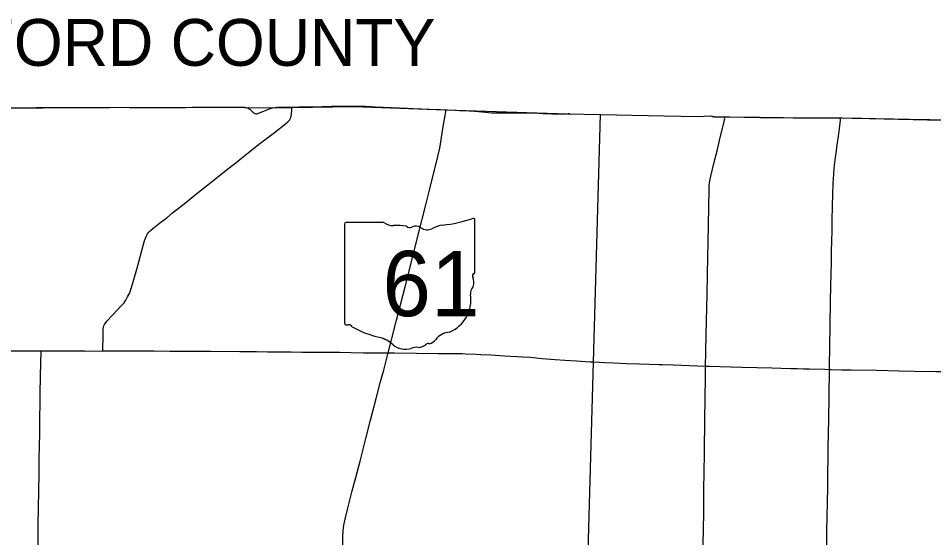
# Model space of a CAD drawing. Extents: x 1815539 to 1947826, y 273303 to 993194.
# Drawn here: x 1872474 to 1891996, y 979080 to 990160 of the extents above; entities that cross this region are included whole.
import ezdxf

# ---------------------------------------------------------------- set-up
doc = ezdxf.new("R2010")
doc.units = 0
for name, color, linetype in [('GM_X_Adjacent_County_Text', 7, 'Continuous'), ('GM_X_County', 7, 'Continuous'), ('GM_X_County_Road', 7, 'Continuous'), ('GM_X_State_Route', 7, 'Continuous'), ('GM_X_Township', 7, 'Continuous'), ('GM_X_Township_Road', 7, 'Continuous'), ('SC_Shading3', 7, 'Continuous')]:
    doc.layers.add(name, color=color, linetype=linetype)

msp = doc.modelspace()

# ---------------------------------------------------------------- linework, layer by layer
at = {"layer": 'GM_X_County'}
msp.add_lwpolyline([(1871661, 988243), (1875677, 988261), (1877300, 988258), (1877944, 988247), (1878309, 988257), (1879625, 988278), (1881591, 988207), (1884186, 988121), (1884889, 988110), (1886245, 988079), (1886959, 988065), (1887247, 988078), (1887277, 988068), (1887305, 988061), (1887332, 988057), (1887406, 988055), (1887534, 988056), (1887954, 988052), (1888291, 988047), (1888567, 988043), (1888789, 988041), (1889241, 988035), (1890006, 988038), (1892176, 987990)], dxfattribs=at)
at = {"layer": 'GM_X_County_Road'}
for points in [[(1871661, 988242), (1871757, 988241), (1871923, 988244), (1872250, 988251), (1872857, 988256), (1873350, 988258), (1873629, 988258), (1873925, 988259), (1874253, 988259), (1874417, 988258), (1874663, 988261), (1874844, 988260), (1875139, 988257), (1875402, 988259), (1875632, 988258), (1875672, 988258)], [(1875672, 988258), (1875796, 988259), (1876042, 988260), (1876174, 988261), (1876404, 988261), (1876617, 988261), (1876880, 988261), (1877143, 988262), (1877257, 988263)], [(1887133, 982742), (1887138, 983036), (1887145, 983413), (1887162, 984266), (1887174, 984709), (1887183, 985054), (1887195, 985743), (1887201, 986153), (1887205, 986497), (1887210, 986595), (1887222, 986692), (1887240, 986789), (1887318, 987091), (1887384, 987361), (1887446, 987616), (1887528, 987951), (1887538, 988001), (1887539, 988021), (1887538, 988035), (1887537, 988057)], [(1887251, 988079), (1887281, 988069), (1887308, 988062), (1887336, 988058), (1887410, 988056), (1887537, 988057)], [(1889775, 982670), (1889775, 982731), (1889783, 983158), (1889789, 983601), (1889799, 984143), (1889810, 984733), (1889814, 984914), (1889818, 985176), (1889823, 985422), (1889829, 985618), (1889831, 985749), (1889832, 985864), (1889838, 986143), (1889847, 986405), (1889854, 986635), (1889864, 986832), (1889874, 986963), (1889889, 987077), (1889905, 987190), (1889919, 987287), (1889937, 987450), (1889971, 987693), (1890004, 987921), (1890008, 987985), (1890006, 987998), (1890002, 988008), (1889995, 988022), (1889986, 988034)], [(1871633, 983066), (1871767, 983066), (1872276, 983066), (1872489, 983068), (1872915, 983067), (1872959, 983067)], [(1872883, 977728), (1872885, 977952), (1872887, 978231), (1872890, 978559), (1872895, 979018), (1872900, 979346), (1872916, 980444), (1872921, 980789), (1872925, 981002), (1872930, 981330), (1872932, 981494), (1872936, 981707), (1872938, 981870), (1872943, 982198), (1872947, 982477), (1872954, 982854), (1872958, 983018), (1872958, 983035), (1872959, 983067)], [(1872959, 983067), (1873193, 983066), (1873489, 983064), (1873899, 983064), (1874243, 983062), (1874277, 983063)], [(1874277, 983063), (1874390, 983063), (1874964, 983063), (1875374, 983063), (1875702, 983061), (1876063, 983060), (1876572, 983057), (1877195, 983051), (1877555, 983049), (1877785, 983048), (1877916, 983047), (1878293, 983044), (1878523, 983041), (1878998, 983036), (1879326, 983034), (1879572, 983030), (1879834, 983026), (1880113, 983025), (1880309, 983024), (1880352, 983024), (1880363, 983024)], [(1887061, 977710), (1887063, 977813), (1887072, 978453), (1887082, 978978), (1887085, 979224), (1887088, 979339), (1887092, 979534), (1887093, 979696), (1887094, 979792), (1887097, 980100), (1887106, 980871), (1887117, 981642), (1887121, 982003), (1887131, 982544), (1887133, 982724), (1887133, 982742)], [(1889705, 978226), (1889707, 978335), (1889710, 978646), (1889714, 978942), (1889719, 979221), (1889736, 980140), (1889740, 980484), (1889743, 980763), (1889745, 980993), (1889754, 981320), (1889760, 981599), (1889766, 982092), (1889775, 982670)], [(1889775, 982670), (1889810, 982669), (1890039, 982664), (1890236, 982660), (1890777, 982650), (1891253, 982641), (1891581, 982635), (1892040, 982626), (1892187, 982623), (1892597, 982617), (1893007, 982610), (1893384, 982604), (1893613, 982600), (1893744, 982597), (1894021, 982589), (1894087, 982587), (1894268, 982583), (1894530, 982582), (1894793, 982578), (1894891, 982575), (1894907, 982574), (1894932, 982573)]]:
    msp.add_lwpolyline(points, dxfattribs=at)
at = {"layer": 'GM_X_State_Route'}
for points in [[(1881240, 986494), (1881241, 986497), (1881334, 986863), (1881422, 987213), (1881461, 987389), (1881493, 987567), (1881531, 987810), (1881599, 988208)], [(1880540, 983720), (1880575, 983857), (1880721, 984429), (1880849, 984938), (1881003, 985542), (1881164, 986179), (1881226, 986434), (1881240, 986494)], [(1880266, 982653), (1880282, 982713), (1880363, 983024), (1880434, 983300), (1880540, 983720)], [(1879887, 981197), (1879988, 981586), (1880058, 981856), (1880107, 982046), (1880194, 982380), (1880234, 982531), (1880266, 982653)], [(1879384, 977403), (1879392, 977559), (1879402, 977887), (1879403, 978084), (1879397, 978543), (1879395, 978855), (1879397, 979101), (1879405, 979231), (1879419, 979345), (1879443, 979474), (1879492, 979681), (1879595, 980078), (1879670, 980363), (1879762, 980712), (1879887, 981197)]]:
    msp.add_lwpolyline(points, dxfattribs=at)
at = {"layer": 'GM_X_Township'}
msp.add_lwpolyline([(1884254, 961672), (1884396, 966955), (1884454, 969588), (1884489, 972257), (1884586, 977269), (1884741, 982824), (1884889, 988110)], dxfattribs=at)
at = {"layer": 'GM_X_Township_Road'}
for points in [[(1876419, 986529), (1876483, 986580), (1876585, 986662), (1876827, 986858), (1876942, 986950), (1877110, 987080), (1877162, 987121), (1877302, 987234), (1877599, 987467), (1877936, 987727), (1878170, 987907), (1878220, 987949), (1878254, 987985), (1878272, 988012), (1878286, 988042), (1878296, 988073), (1878301, 988105), (1878306, 988220), (1878305, 988238), (1878304, 988253), (1878301, 988267)], [(1877257, 988263), (1877303, 988261), (1877325, 988258), (1877350, 988253), (1877377, 988243), (1877390, 988236), (1877413, 988218), (1877468, 988164), (1877493, 988143), (1877506, 988134), (1877520, 988127), (1877536, 988123), (1877552, 988123), (1877568, 988126), (1877583, 988130), (1877599, 988135), (1877691, 988171), (1877723, 988184), (1877829, 988225), (1877852, 988234), (1877901, 988248), (1877946, 988257)], [(1877946, 988257), (1877965, 988260), (1877973, 988260), (1877996, 988262), (1878029, 988264)], [(1878029, 988264), (1878045, 988265), (1878127, 988265), (1878301, 988267)], [(1878301, 988267), (1878457, 988268), (1878956, 988279), (1879160, 988283), (1879620, 988289)], [(1879620, 988289), (1879732, 988288), (1879880, 988284), (1879995, 988279), (1880093, 988274), (1880765, 988244), (1880896, 988237), (1881073, 988227), (1881237, 988220), (1881481, 988211), (1881559, 988209), (1881599, 988208)], [(1881599, 988208), (1881624, 988207), (1881788, 988198), (1881810, 988197)], [(1881810, 988197), (1881886, 988194), (1881979, 988190)], [(1881979, 988190), (1882082, 988186), (1882145, 988183), (1882209, 988181), (1882291, 988175), (1882356, 988168), (1882437, 988157), (1882503, 988151), (1882572, 988146), (1882642, 988145)], [(1882642, 988145), (1882730, 988143), (1882928, 988145), (1883051, 988143), (1883208, 988144), (1883339, 988142), (1883421, 988141), (1883568, 988136), (1883667, 988132), (1883847, 988125), (1883856, 988125)], [(1883856, 988125), (1883978, 988121), (1884093, 988120), (1884159, 988122), (1884208, 988126), (1884236, 988129)], [(1887537, 988057), (1887640, 988058), (1887958, 988053)], [(1887958, 988053), (1888295, 988048)], [(1888295, 988048), (1888461, 988045), (1888570, 988043)], [(1888570, 988043), (1888592, 988043), (1888773, 988042), (1888793, 988042)], [(1888793, 988042), (1889002, 988040), (1889239, 988037)], [(1889239, 988037), (1889574, 988034), (1889784, 988034), (1889833, 988034), (1889931, 988034), (1889986, 988034)], [(1889986, 988034), (1890029, 988033), (1890044, 988033)], [(1890044, 988033), (1890260, 988031), (1890461, 988028), (1890755, 988021), (1891138, 988014), (1891484, 988007), (1891917, 987998), (1892166, 987992)], [(1874277, 983063), (1874277, 983094), (1874280, 983373), (1874283, 983521), (1874290, 983569), (1874299, 983600), (1874313, 983630), (1874330, 983658), (1874361, 983696), (1874485, 983827), (1874677, 984030), (1874729, 984093), (1874765, 984148), (1874806, 984218), (1874843, 984292), (1874868, 984352), (1874887, 984415), (1874934, 984589), (1874998, 984809), (1875043, 984967), (1875108, 985204), (1875160, 985394), (1875186, 985472), (1875206, 985517), (1875231, 985559), (1875260, 985598), (1875294, 985634), (1875344, 985676), (1875486, 985787), (1875638, 985905), (1875765, 986007), (1876008, 986202), (1876213, 986366), (1876315, 986448), (1876419, 986529)], [(1880363, 983024), (1880500, 983022), (1881436, 983011), (1881764, 983007), (1881829, 983009), (1881943, 983007), (1882009, 983004), (1882238, 982997), (1882336, 982991), (1882549, 982979), (1882844, 982959), (1883237, 982940), (1883401, 982928), (1883515, 982917), (1883645, 982901), (1883923, 982882), (1884133, 982869), (1884376, 982855), (1884671, 982833), (1884736, 982831)], [(1884736, 982831), (1884862, 982822), (1884867, 982822)], [(1884867, 982822), (1884978, 982815)], [(1884978, 982815), (1885165, 982807), (1885444, 982796), (1885723, 982788), (1886134, 982776), (1886216, 982773), (1886445, 982766), (1887133, 982742)], [(1887133, 982742), (1887217, 982739), (1887906, 982720), (1888546, 982700), (1888940, 982691), (1889088, 982686), (1889219, 982683), (1889350, 982682), (1889678, 982672), (1889775, 982670)]]:
    msp.add_lwpolyline(points, dxfattribs=at)
at = {"layer": 'SC_Shading3'}
for p, q in [((1879429, 985769), (1879429, 983656)), ((1880272, 985805), (1879456, 985805)), ((1882213, 984752), (1882213, 985858)), ((1882213, 984753), (1882213, 984752))]:
    msp.add_line(p, q, dxfattribs=at)
for centre, radius, start, end in [((1879461, 985774), 32.3, 98.1301, 188.1301), ((1880466, 986051), 313, 231.6195, 271.1119), ((1880570, 984619), 1123, 80.4867, 94.9883), ((1880825, 985785), 90.3, 219.7921, 297.1024), ((1880957, 985540), 188, 54.4667, 119.1411), ((1881598, 985160), 594, 97.3462, 120.7689), ((1881222, 988687), 2953, 275.8445, 288.9065), ((1882182, 985862), 31, 351.8621, 97.738), ((1881199, 985875), 226, 233.8562, 294.8282), ((1882180, 984748), 33.2, 289.6038, 7.7341), ((1882206, 984671), 48, 107.944, 210.337), ((1881901, 984531), 288, 340.033, 23.6496), ((1882324, 984290), 210, 136.8065, 186.9296), ((1881387, 984149), 739, 292.3089, 8.9858), ((1879461, 983651), 32.5, 171.9584, 258.3066), ((1879466, 983867), 248, 267.339, 280.6039), ((1879517, 983534), 89.5, 29.7484, 93.2717), ((1880648, 985433), 2132, 240.4129, 257.1985), ((1881698, 983062), 404, 94.4031, 142.5768), ((1880012, 982706), 667, 47.1842, 75.836), ((1880733, 983523), 423, 230.7004, 286.2918), ((1881009, 983365), 226, 268.777, 315.5493), ((1881213, 983160), 63.5, 65.7517, 132.6484), ((1881186, 983451), 239, 282.8732, 323.2771), ((1880978, 982793), 348, 85.6951, 111.2099)]:
    msp.add_arc(centre, radius, start, end, dxfattribs=at)

# ---------------------------------------------------------------- texts
at = {"layer": 'GM_X_Adjacent_County_Text'}
msp.add_text('CRAWFORD COUNTY', height=1000, dxfattribs=at).set_placement((1867478, 989145))
at = {"layer": 'SC_Shading3'}
msp.add_text('61', height=1392.2, dxfattribs=at).set_placement((1880239, 983805))

doc.saveas('drawing.dxf')
